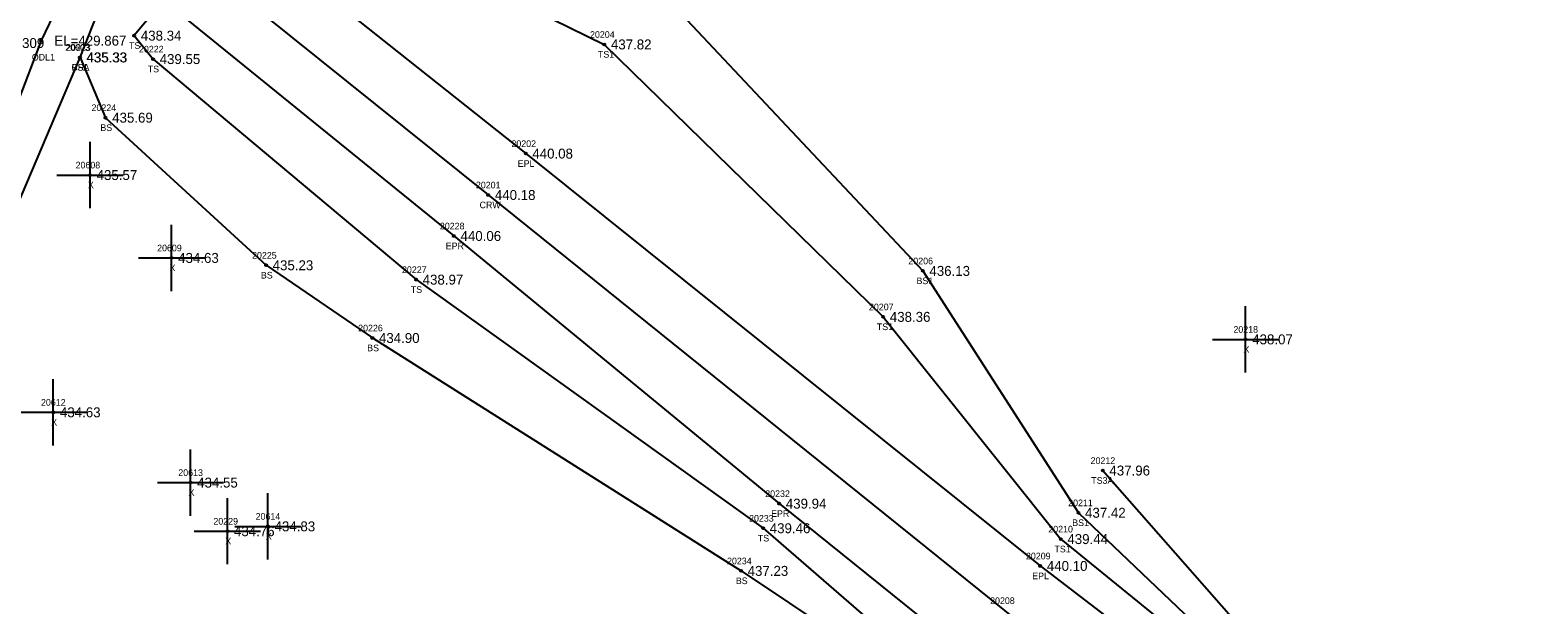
# Model space of a CAD drawing. Extents: x 1613836 to 1615109, y 777151 to 778248.
# Drawn here: x 1614452.4 to 1614680.1, y 777585.5 to 777672.3 of the extents above; entities that cross this region are included whole.
import ezdxf

# ---------------------------------------------------------------- set-up
doc = ezdxf.new("R2010")
doc.units = 0
for name, color, linetype in [('RD_DTM_BkLn1', 7, 'Continuous'), ('RD_DTM_BkLn2', 7, 'Continuous'), ('RD_DTM_BkLn_txCode', 7, 'Continuous'), ('RD_EX_H2O', 7, 'Continuous'), ('RD_EX_H2O_txCode', 7, 'Continuous'), ('RD_EX_Misc', 7, 'Continuous'), ('RD_EX_Misc_txCode', 7, 'Continuous'), ('RD_EX_Road', 7, 'Continuous'), ('RD_EX_Road_txCode', 7, 'Continuous'), ('RD_EX_TX_H2O_ELEV', 7, 'Continuous'), ('RD_EX_TX_Misc_ELEV', 7, 'Continuous'), ('RD_EX_TX_Road_ELEV', 7, 'Continuous'), ('RD_HC_Survey_ELEV', 7, 'Continuous'), ('RD_HC_Survey_txCode', 7, 'Continuous'), ('RD_SMD_Locator', 7, 'Continuous')]:
    doc.layers.add(name, color=color, linetype=linetype)

msp = doc.modelspace()

# ---------------------------------------------------------------- linework, layer by layer
at = {"layer": 'RD_DTM_BkLn1'}
msp.add_lwpolyline([(1614479.01, 777681.63), (1614521.59, 777647.42), (1614599.56, 777584.67), (1614677.14, 777521.99), (1614754.7, 777459.32), (1614832.45, 777396.45), (1614909.52, 777332.99), (1614951.1, 777299.39), (1614987.2, 777270.31), (1615065.15, 777207.54)], dxfattribs=at)
at = {"layer": 'RD_DTM_BkLn2'}
for points in [[(1614480.98, 777699.79), (1614497.59, 777703), (1614522.19, 777696.07), (1614543.87, 777680.98), (1614547.65, 777678.09), (1614587.23, 777635.96), (1614610.74, 777599.44), (1614633.11, 777578.17), (1614686.46, 777534.25), (1614763.32, 777471.34), (1614841.29, 777408.4), (1614909.19, 777352.07)], [(1614487.8, 777694.98), (1614468.11, 777671.48), (1614470.95, 777667.94), (1614510.68, 777634.64), (1614563.11, 777597.11), (1614590.8, 777573.1), (1614668.37, 777511.43), (1614746.83, 777448.93), (1614824, 777386.05), (1614902.11, 777323.38), (1614943.6, 777288.77), (1614978.33, 777258.85), (1615057.35, 777197.32)], [(1614487.8, 777694.98), (1614492.09, 777693.24), (1614539.12, 777670.15), (1614581.25, 777629.02), (1614608.07, 777595.47), (1614631.79, 777576.16), (1614684.94, 777532.19), (1614761.79, 777469.29), (1614840.42, 777406.78), (1614908.46, 777350.38), (1614912.05, 777350.16), (1614911.85, 777355.47)], [(1614459.93, 777668.19), (1614463.78, 777659.09), (1614488.02, 777636.81), (1614504.08, 777625.83), (1614559.77, 777590.67), (1614588.99, 777571.17), (1614666.25, 777508.81), (1614744.8, 777446.03), (1614822.12, 777383.78), (1614899.86, 777320.65), (1614938.98, 777288.55), (1614940.53, 777287.22)], [(1614614.42, 777605.82), (1614635.25, 777582.12), (1614690.07, 777537.42), (1614767.2, 777474.86), (1614846.75, 777413.92), (1614911.85, 777355.47)]]:
    msp.add_lwpolyline(points, dxfattribs=at)
at = {"layer": 'RD_EX_H2O'}
for points in [[(1614458.98, 777681.06), (1614454.05, 777670.72), (1614436.75, 777625.46)], [(1614463.06, 777676.24), (1614459.87, 777668.19), (1614440.89, 777623.61)]]:
    msp.add_lwpolyline(points, dxfattribs=at)
at = {"layer": 'RD_EX_Misc'}
for p, q in [((1614461.43, 777645.43), (1614461.43, 777655.43)), ((1614456.43, 777650.43), (1614466.43, 777650.43)), ((1614473.75, 777632.92), (1614473.75, 777642.92)), ((1614468.75, 777637.92), (1614478.75, 777637.92)), ((1614635.99, 777620.62), (1614635.99, 777630.62)), ((1614630.99, 777625.62), (1614640.99, 777625.62)), ((1614455.89, 777609.61), (1614455.89, 777619.61)), ((1614450.89, 777614.61), (1614460.89, 777614.61)), ((1614476.62, 777599), (1614476.62, 777609)), ((1614471.62, 777604), (1614481.62, 777604)), ((1614488.31, 777592.39), (1614488.31, 777602.39)), ((1614482.18, 777591.66), (1614482.18, 777601.66)), ((1614483.31, 777597.39), (1614493.31, 777597.39)), ((1614477.18, 777596.66), (1614487.18, 777596.66))]:
    msp.add_line(p, q, dxfattribs=at)
at = {"layer": 'RD_EX_Road'}
for points in [[(1614484.15, 777687.93), (1614479.01, 777681.63), (1614474.14, 777675.5), (1614516.4, 777641.23), (1614565.54, 777600.82), (1614593.96, 777577.93), (1614671.57, 777514.59), (1614748.82, 777451.94), (1614826.23, 777388.93), (1614903.92, 777325.97), (1614945.38, 777292), (1614981.73, 777262.81), (1615059.73, 777200.12)], [(1614484.15, 777687.93), (1614527.25, 777653.67), (1614604.97, 777591.41), (1614629.13, 777572.93), (1614683.14, 777529.85), (1614759.91, 777466.85), (1614838.21, 777403.78), (1614915.19, 777340.18), (1614934.98, 777324.5), (1615070.79, 777214.66)]]:
    msp.add_lwpolyline(points, dxfattribs=at)
at = {"layer": 'RD_SMD_Locator'}
for centre in [(1614454.05, 777670.72), (1614468.11, 777671.48), (1614539.12, 777670.15), (1614459.87, 777668.19), (1614459.93, 777668.19), (1614470.95, 777667.94), (1614463.78, 777659.09), (1614527.25, 777653.67), (1614461.43, 777650.43), (1614521.59, 777647.42), (1614516.4, 777641.23), (1614473.75, 777637.92), (1614488.02, 777636.81), (1614587.23, 777635.96), (1614510.68, 777634.64), (1614581.25, 777629.02), (1614504.08, 777625.83), (1614635.99, 777625.62), (1614455.89, 777614.61), (1614476.62, 777604), (1614614.42, 777605.82), (1614565.54, 777600.82), (1614610.74, 777599.44), (1614488.31, 777597.39), (1614563.11, 777597.11), (1614482.18, 777596.66), (1614608.07, 777595.47), (1614559.77, 777590.67), (1614604.97, 777591.41)]:
    msp.add_circle(centre, 0.15, dxfattribs=at)

# ---------------------------------------------------------------- texts
at = {"layer": 'RD_DTM_BkLn_txCode'}
for s, p in [('20223', (1614457.81, 777669.19)), ('TS', (1614467.32, 777669.48)), ('20204', (1614536.96, 777671.15)), ('20222', (1614468.83, 777668.94)), ('TS1', (1614538.16, 777668.15)), ('BSA', (1614458.66, 777666.19)), ('TS', (1614470.15, 777665.94)), ('20224', (1614461.66, 777660.09)), ('BS', (1614463, 777657.09)), ('20225', (1614485.91, 777637.81)), ('20227', (1614508.56, 777635.64)), ('20206', (1614585.05, 777636.96)), ('BS', (1614487.24, 777634.81)), ('BS1', (1614586.28, 777633.96)), ('TS', (1614509.89, 777632.64)), ('20207', (1614579.1, 777630.02)), ('20226', (1614501.94, 777626.83)), ('TS1', (1614580.29, 777627.02)), ('BS', (1614503.3, 777623.83)), ('20212', (1614612.58, 777606.82)), ('TS3A', (1614612.68, 777603.82)), ('20211', (1614609.19, 777600.44)), ('20233', (1614560.99, 777598.11)), ('20210', (1614606.19, 777596.47)), ('BS1', (1614609.8, 777597.44)), ('TS', (1614562.31, 777595.11)), ('TS1', (1614607.11, 777593.47)), ('20234', (1614557.66, 777591.67)), ('BS', (1614558.99, 777588.67))]:
    msp.add_text(s, height=1, dxfattribs=at).set_placement(p)
at = {"layer": 'RD_EX_H2O_txCode'}
for s, p in [('20603', (1614457.69, 777669.19)), ('ODL1', (1614452.64, 777667.72)), ('CRL', (1614458.64, 777666.19))]:
    msp.add_text(s, height=1, dxfattribs=at).set_placement(p)
at = {"layer": 'RD_EX_Misc_txCode'}
for s, p in [('20608', (1614459.25, 777651.43)), ('X', (1614461.11, 777648.43)), ('20609', (1614471.57, 777638.92)), ('X', (1614473.44, 777635.92)), ('20218', (1614634.15, 777626.62)), ('X', (1614635.67, 777623.62)), ('20612', (1614454.03, 777615.61)), ('X', (1614455.57, 777612.61)), ('20613', (1614474.77, 777605)), ('X', (1614476.31, 777602)), ('20229', (1614480.07, 777597.66)), ('20614', (1614486.45, 777598.39)), ('X', (1614481.87, 777594.66)), ('X', (1614487.99, 777595.39))]:
    msp.add_text(s, height=1, dxfattribs=at).set_placement(p)
at = {"layer": 'RD_EX_Road_txCode'}
for s, p in [('20202', (1614525.09, 777654.67)), ('EPL', (1614526.04, 777651.67)), ('20228', (1614514.28, 777642.23)), ('EPR', (1614515.17, 777639.23)), ('20232', (1614563.43, 777601.82)), ('EPR', (1614564.32, 777598.82)), ('20209', (1614602.81, 777592.41)), ('EPL', (1614603.76, 777589.41))]:
    msp.add_text(s, height=1, dxfattribs=at).set_placement(p)
at = {"layer": 'RD_EX_TX_H2O_ELEV'}
for s, p in [('EL=430.309', (1614443.64, 777669.61)), ('EL=429.867', (1614456.05, 777669.97)), ('435.33', (1614460.87, 777667.44))]:
    msp.add_text(s, height=1.5, dxfattribs=at).set_placement(p)
at = {"layer": 'RD_EX_TX_Misc_ELEV'}
for s, p in [('438.34', (1614469.11, 777670.73)), ('437.82', (1614540.12, 777669.4)), ('435.33', (1614460.93, 777667.44)), ('439.55', (1614471.95, 777667.19)), ('435.69', (1614464.78, 777658.34)), ('435.57', (1614462.43, 777649.68)), ('434.63', (1614474.75, 777637.17)), ('435.23', (1614489.02, 777636.06)), ('436.13', (1614588.23, 777635.21)), ('438.97', (1614511.68, 777633.89)), ('438.36', (1614582.25, 777628.27)), ('434.90', (1614505.08, 777625.08)), ('438.07', (1614636.99, 777624.87)), ('434.63', (1614456.89, 777613.86)), ('437.96', (1614615.42, 777605.07)), ('434.55', (1614477.62, 777603.25)), ('437.42', (1614611.74, 777598.69)), ('434.76', (1614483.18, 777595.91)), ('434.83', (1614489.31, 777596.64)), ('439.46', (1614564.11, 777596.36)), ('439.44', (1614609.07, 777594.72)), ('437.23', (1614560.77, 777589.92))]:
    msp.add_text(s, height=1.5, dxfattribs=at).set_placement(p)
at = {"layer": 'RD_EX_TX_Road_ELEV'}
for s, p in [('440.08', (1614528.25, 777652.92)), ('440.06', (1614517.4, 777640.48)), ('439.94', (1614566.54, 777600.07)), ('440.10', (1614605.97, 777590.66))]:
    msp.add_text(s, height=1.5, dxfattribs=at).set_placement(p)
at = {"layer": 'RD_HC_Survey_ELEV'}
msp.add_text('440.18', height=1.5, dxfattribs=at).set_placement((1614522.59, 777646.67))
at = {"layer": 'RD_HC_Survey_txCode'}
for s, p in [('20201', (1614519.72, 777648.42)), ('CRW', (1614520.28, 777645.42)), ('20208', (1614597.4, 777585.67))]:
    msp.add_text(s, height=1, dxfattribs=at).set_placement(p)

doc.saveas('drawing.dxf')
